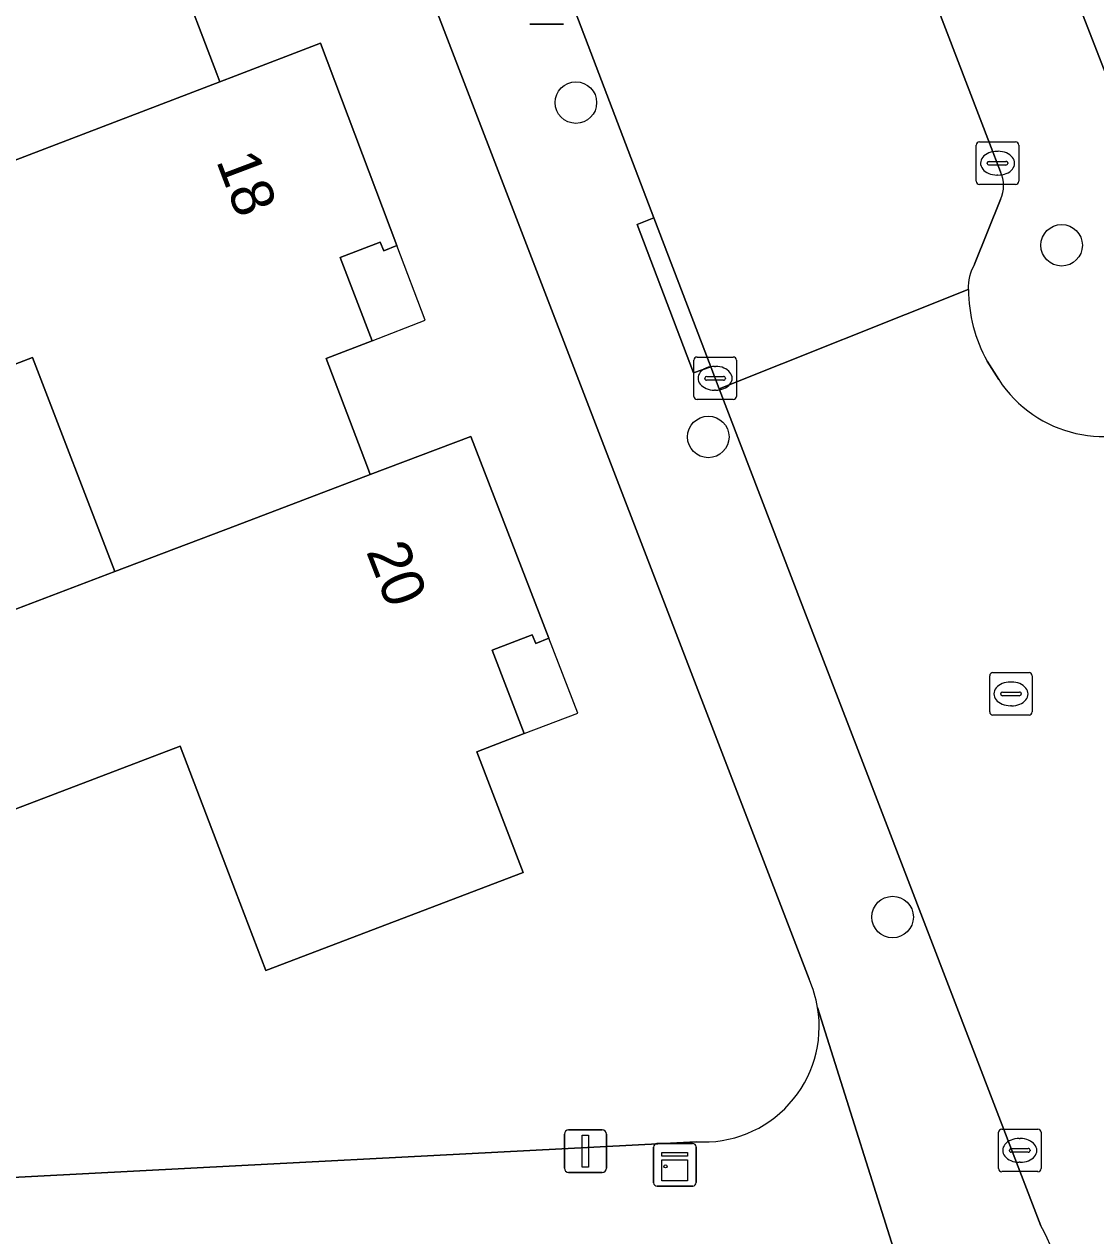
# Model space of a CAD drawing. Extents: x 159262 to 160143, y 383399 to 384319.
# Drawn here: x 159495.03 to 159520.25, y 383645.59 to 383674.12 of the extents above; entities that cross this region are included whole.
import ezdxf

# ---------------------------------------------------------------- set-up
doc = ezdxf.new("R2010")
doc.units = 0
for name, color, linetype in [('IMGEO_Boom', 7, 'Continuous'), ('IMGEO_Erf', 7, 'Continuous'), ('IMGEO_Kast', 7, 'Continuous'), ('IMGEO_Kolk', 7, 'Continuous'), ('IMGEO_Lichtmast', 7, 'Continuous'), ('IMGEO_Pand', 7, 'Continuous'), ('IMGEO_Pand_nummerreeks', 7, 'Continuous'), ('IMGEO_Pand_overbouw', 7, 'Continuous'), ('IMGEO_Rijbaan_lokaal_gesloten', 7, 'Continuous'), ('IMGEO_Rijbaan_lokaal_open', 7, 'Continuous'), ('IMGEO_Rioolput', 7, 'Continuous'), ('IMGEO_Voetpad_open', 7, 'Continuous')]:
    doc.layers.add(name, color=color, linetype=linetype)

msp = doc.modelspace()

# ---------------------------------------------------------------- linework, layer by layer
at = {"layer": 'IMGEO_Boom'}
for centre in [(159508.012, 383672.274), (159519.444, 383668.915), (159511.128, 383664.403), (159515.465, 383653.098)]:
    msp.add_circle(centre, 0.489, dxfattribs=at)
at = {"layer": 'IMGEO_Erf'}
for points in [[(159524.222, 383708.733), (159517.215, 383705.993), (159516.251, 383708.492), (159511.066, 383706.465), (159512.465, 383702.887), (159509.321, 383701.658), (159512.811, 383692.674), (159522.704, 383667.239)], [(159513.499, 383651.634), (159500, 383686.749), (159496.449, 383695.986), (159490.681, 383693.764)], [(159498.598, 383675.488), (159499.565, 383672.949), (159499.634, 383672.767), (159500, 383672.907), (159501.998, 383673.672), (159503.8, 383668.912), (159503.49, 383668.788), (159503.405, 383668.989), (159502.464, 383668.631), (159503.215, 383666.668), (159502.136, 383666.253), (159503.105, 383663.69), (159503.171, 383663.515), (159505.537, 383664.413), (159507.377, 383659.665), (159507.067, 383659.541), (159506.982, 383659.742), (159506.041, 383659.384), (159506.796, 383657.417), (159505.683, 383656.991), (159506.773, 383654.147), (159500.713, 383651.835), (159500, 383653.703), (159498.695, 383657.123), (159492.81, 383654.875)], [(159470.88, 383645.715), (159500, 383647.239), (159510.841, 383647.807)]]:
    msp.add_lwpolyline(points, dxfattribs=at)
msp.add_lwpolyline([(159489.125, 383663.933), (159491.054, 383658.914), (159497.161, 383661.233), (159495.223, 383666.276)], close=True, dxfattribs=at)
for centre, radius, start, end in [((159511.055, 383650.53), 2.682, 9.3498, 24.3004), ((159511.019, 383650.52), 2.719, 266.2475, 9.4403)]:
    msp.add_arc(centre, radius, start, end, dxfattribs=at)
at = {"layer": 'IMGEO_Kast'}
for p, q in [((159509.917, 383647.762), (159510.758, 383647.762)), ((159510.758, 383647.762), (159509.917, 383647.762)), ((159509.842, 383646.837), (159509.842, 383647.678)), ((159509.842, 383647.678), (159509.842, 383646.837)), ((159510.842, 383647.687), (159510.842, 383646.846)), ((159510.842, 383646.846), (159510.842, 383647.687)), ((159510.767, 383646.762), (159509.926, 383646.762)), ((159509.926, 383646.762), (159510.767, 383646.762))]:
    msp.add_line(p, q, dxfattribs=at)
for points in [[(159510.037, 383647.552), (159510.637, 383647.552), (159510.637, 383647.467), (159510.037, 383647.467), (159510.037, 383647.552)], [(159510.037, 383647.377), (159510.637, 383647.377), (159510.637, 383646.888), (159510.037, 383646.888), (159510.037, 383647.377)]]:
    msp.add_lwpolyline(points, dxfattribs=at)
msp.add_circle((159510.121, 383647.226), 0.0377, dxfattribs=at)
for centre, start, end in [((159509.92, 383647.684), 92.4484, 184.2845), ((159509.92, 383647.684), 92.4484, 184.2845), ((159510.764, 383647.684), 2.4484, 94.2845), ((159510.764, 383647.684), 2.4484, 94.2845), ((159509.92, 383646.84), 182.4484, 274.2845), ((159509.92, 383646.84), 182.4484, 274.2845), ((159510.764, 383646.84), 272.4484, 4.2845), ((159510.764, 383646.84), 272.4484, 4.2845)]:
    msp.add_arc(centre, 0.0779, start, end, dxfattribs=at)
at = {"layer": 'IMGEO_Kolk'}
for p, q in [((159517.435, 383670.422), (159517.435, 383671.274)), ((159517.51, 383671.348), (159518.362, 383671.348)), ((159517.923, 383671.128), (159517.948, 383671.128)), ((159518.436, 383671.274), (159518.436, 383670.422)), ((159517.694, 383670.842), (159517.694, 383670.854)), ((159517.737, 383670.891), (159518.135, 383670.891)), ((159518.178, 383670.854), (159518.178, 383670.842)), ((159518.132, 383670.805), (159517.734, 383670.805)), ((159517.946, 383670.568), (159517.921, 383670.568)), ((159518.362, 383670.348), (159517.51, 383670.348)), ((159510.863, 383666.284), (159511.715, 383666.284)), ((159510.788, 383665.358), (159510.788, 383666.21)), ((159511.276, 383666.064), (159511.301, 383666.064)), ((159511.789, 383666.21), (159511.789, 383665.358)), ((159511.047, 383665.778), (159511.047, 383665.79)), ((159511.485, 383665.741), (159511.087, 383665.741)), ((159511.09, 383665.827), (159511.488, 383665.827)), ((159511.531, 383665.79), (159511.531, 383665.778)), ((159511.299, 383665.504), (159511.274, 383665.504)), ((159511.715, 383665.284), (159510.863, 383665.284)), ((159517.958, 383647.176), (159517.958, 383648.028)), ((159518.033, 383648.102), (159518.885, 383648.102)), ((159518.959, 383648.028), (159518.959, 383647.176)), ((159518.446, 383647.882), (159518.471, 383647.882)), ((159518.217, 383647.596), (159518.217, 383647.608)), ((159518.655, 383647.559), (159518.257, 383647.559)), ((159518.26, 383647.645), (159518.658, 383647.645)), ((159518.701, 383647.608), (159518.701, 383647.596)), ((159518.469, 383647.322), (159518.444, 383647.322)), ((159518.885, 383647.102), (159518.033, 383647.102))]:
    msp.add_line(p, q, dxfattribs=at)
for points in [[(159517.435, 383670.422), (159517.435, 383671.274)], [(159517.51, 383671.348), (159518.362, 383671.348)], [(159518.436, 383671.274), (159518.436, 383670.422)], [(159518.362, 383670.348), (159517.51, 383670.348)], [(159510.863, 383666.284), (159511.715, 383666.284)], [(159510.788, 383665.358), (159510.788, 383666.21)], [(159511.789, 383666.21), (159511.789, 383665.358)], [(159511.715, 383665.284), (159510.863, 383665.284)], [(159517.958, 383647.176), (159517.958, 383648.028)], [(159518.033, 383648.102), (159518.885, 383648.102)], [(159518.959, 383648.028), (159518.959, 383647.176)], [(159518.885, 383647.102), (159518.033, 383647.102)]]:
    msp.add_lwpolyline(points, dxfattribs=at)
for centre, radius, start, end in [((159517.512, 383671.272), 0.0765, 91.552, 178.448), ((159517.512, 383671.272), 0.0765, 91.552, 178.448), ((159518.36, 383671.272), 0.0765, 1.552, 88.448), ((159518.36, 383671.272), 0.0765, 1.552, 88.448), ((159517.734, 383670.851), 0.0403, 85.8775, 175.7526), ((159517.731, 383670.841), 0.0366, 178.938, 274.7102), ((159518.135, 383670.848), 0.043, 264.8664, 352.4533), ((159518.139, 383670.853), 0.0386, 1.7309, 96.639), ((159517.512, 383670.424), 0.0765, 181.552, 268.448), ((159517.512, 383670.424), 0.0765, 181.552, 268.448), ((159518.36, 383670.424), 0.0765, 271.552, 358.448), ((159518.36, 383670.424), 0.0765, 271.552, 358.448), ((159510.865, 383666.208), 0.0765, 91.552, 178.448), ((159510.865, 383666.208), 0.0765, 91.552, 178.448), ((159511.713, 383666.208), 0.0765, 1.552, 88.448), ((159511.713, 383666.208), 0.0765, 1.552, 88.448), ((159511.087, 383665.787), 0.0403, 85.8775, 175.7526), ((159511.084, 383665.777), 0.0366, 178.938, 274.7102), ((159511.488, 383665.784), 0.043, 264.8664, 352.4533), ((159511.492, 383665.789), 0.0386, 1.7309, 96.639), ((159510.865, 383665.36), 0.0765, 181.552, 268.448), ((159510.865, 383665.36), 0.0765, 181.552, 268.448), ((159511.713, 383665.36), 0.0765, 271.552, 358.448), ((159511.713, 383665.36), 0.0765, 271.552, 358.448), ((159518.035, 383648.026), 0.0765, 91.552, 178.448), ((159518.035, 383648.026), 0.0765, 91.552, 178.448), ((159518.883, 383648.026), 0.0765, 1.552, 88.448), ((159518.883, 383648.026), 0.0765, 1.552, 88.448), ((159518.257, 383647.605), 0.0403, 85.8775, 175.7526), ((159518.254, 383647.595), 0.0366, 178.938, 274.7102), ((159518.658, 383647.602), 0.043, 264.8664, 352.4533), ((159518.662, 383647.607), 0.0386, 1.7309, 96.639), ((159518.035, 383647.178), 0.0765, 181.552, 268.448), ((159518.035, 383647.178), 0.0765, 181.552, 268.448), ((159518.883, 383647.178), 0.0765, 271.552, 358.448), ((159518.883, 383647.178), 0.0765, 271.552, 358.448)]:
    msp.add_arc(centre, radius, start, end, dxfattribs=at)
for centre, major_axis, ratio, start_param, end_param in [((159517.922, 383670.848), (-0.387, 0.002), 0.722429, 4.712389, 7.853982), ((159517.947, 383670.848), (-0.39, 0.002), 0.717154, 1.570796, 4.712389), ((159511.275, 383665.784), (-0.387, 0.002), 0.722429, 4.712389, 7.853982), ((159511.3, 383665.784), (-0.39, 0.002), 0.717154, 1.570796, 4.712389), ((159518.445, 383647.602), (-0.387, 0.002), 0.722429, 4.712389, 7.853982), ((159518.47, 383647.602), (-0.39, 0.002), 0.717154, 1.570796, 4.712389)]:
    msp.add_ellipse(centre, major_axis=major_axis, ratio=ratio, start_param=start_param, end_param=end_param, dxfattribs=at)
at = {"layer": 'IMGEO_Lichtmast'}
for p, q in [((159507.719, 383674.12), (159506.929, 383674.12)), ((159506.929, 383674.12), (159507.719, 383674.12)), ((159507.842, 383648.084), (159508.632, 383648.084)), ((159508.632, 383648.084), (159507.842, 383648.084)), ((159507.742, 383647.184), (159507.742, 383647.984)), ((159507.742, 383647.984), (159507.742, 383647.184)), ((159508.732, 383647.984), (159508.732, 383647.184)), ((159508.732, 383647.184), (159508.732, 383647.984)), ((159508.632, 383647.084), (159507.842, 383647.084)), ((159507.842, 383647.084), (159508.632, 383647.084))]:
    msp.add_line(p, q, dxfattribs=at)
msp.add_lwpolyline([(159508.162, 383647.959), (159508.312, 383647.959), (159508.312, 383647.209), (159508.162, 383647.209), (159508.162, 383647.959)], dxfattribs=at)
for centre, start, end in [((159507.842, 383647.984), 90, 180), ((159507.842, 383647.984), 90, 180), ((159508.632, 383647.984), 0, 90), ((159508.632, 383647.984), 360, 90), ((159507.842, 383647.184), 180, 270), ((159507.842, 383647.184), 180, 270), ((159508.632, 383647.184), 270, 0), ((159508.632, 383647.184), 270, 0)]:
    msp.add_arc(centre, 0.1, start, end, dxfattribs=at)
at = {"layer": 'IMGEO_Pand'}
for points in [[(159498.598, 383675.488), (159499.696, 383675.913), (159498.941, 383677.872), (159499.882, 383678.23), (159500, 383678.042), (159500.277, 383678.153), (159500, 383678.876), (159498.452, 383682.919), (159496.097, 383682.017), (159490.041, 383679.698), (159483.961, 383677.37), (159485.556, 383673.219), (159491.705, 383675.582), (159493.665, 383670.483), (159499.634, 383672.767), (159499.565, 383672.949)], [(159503.215, 383666.668), (159502.464, 383668.631), (159503.405, 383668.989), (159503.49, 383668.788), (159503.8, 383668.912), (159501.998, 383673.672), (159500, 383672.907), (159499.634, 383672.767), (159493.665, 383670.483), (159487.513, 383668.129), (159489.125, 383663.933), (159495.223, 383666.276), (159497.161, 383661.233), (159500, 383662.311), (159503.171, 383663.515), (159503.105, 383663.69), (159502.136, 383666.253)], [(159505.683, 383656.991), (159506.796, 383657.417), (159506.041, 383659.384), (159506.982, 383659.742), (159507.067, 383659.541), (159507.377, 383659.665), (159505.537, 383664.413), (159503.171, 383663.515), (159500, 383662.311), (159497.161, 383661.233), (159491.054, 383658.914), (159492.632, 383654.807), (159492.81, 383654.875), (159498.695, 383657.123), (159500, 383653.703), (159500.713, 383651.835), (159506.773, 383654.147)]]:
    msp.add_lwpolyline(points, close=True, dxfattribs=at)
at = {"layer": 'IMGEO_Pand_overbouw'}
for points in [[(159503.8, 383668.912), (159503.49, 383668.788), (159503.405, 383668.989), (159502.464, 383668.631), (159503.215, 383666.668), (159504.467, 383667.15)], [(159507.377, 383659.665), (159507.067, 383659.541), (159506.982, 383659.742), (159506.041, 383659.384), (159506.796, 383657.417), (159508.061, 383657.901)]]:
    msp.add_lwpolyline(points, close=True, dxfattribs=at)
at = {"layer": 'IMGEO_Rijbaan_lokaal_gesloten'}
for points in [[(159489.512, 383722.543), (159495.821, 383706.144), (159496.217, 383705.045), (159500, 383695.226), (159500.226, 383694.637), (159502.703, 383688.187), (159504.052, 383684.679), (159504.271, 383684.118), (159506.344, 383678.724), (159507.694, 383675.212), (159509.846, 383669.564), (159511.185, 383666.05), (159511.381, 383665.535), (159517.248, 383667.871)], [(159518.009, 383670.645), (159500.962, 383715.104)], [(159517.397, 383668.469), (159518.008, 383669.995)]]:
    msp.add_lwpolyline(points, dxfattribs=at)
for centre, radius, start, end in [((159517.283, 383670.321), 0.795, 335.7706, 24.0532), ((159518.327, 383667.92), 1.081, 149.4394, 182.5783)]:
    msp.add_arc(centre, radius, start, end, dxfattribs=at)
at = {"layer": 'IMGEO_Rijbaan_lokaal_open'}
for points in [[(159517.248, 383667.871), (159511.381, 383665.535), (159513.341, 383660.438), (159514.686, 383656.939), (159518.958, 383645.83)], [(159517.964, 383665.755), (159517.688, 383666.189)]]:
    msp.add_lwpolyline(points, dxfattribs=at)
for centre, radius, start, end in [((159520.818, 383667.906), 3.57, 180.5674, 208.752), ((159520.44, 383667.363), 2.953, 212.993, 301.1537), ((159514.406, 383643.394), 5.163, 272.5547, 28.154)]:
    msp.add_arc(centre, radius, start, end, dxfattribs=at)
at = {"layer": 'IMGEO_Rioolput'}
for p, q in [((159517.751, 383657.926), (159517.751, 383658.778)), ((159517.826, 383658.852), (159518.678, 383658.852)), ((159518.239, 383658.632), (159518.264, 383658.632)), ((159518.752, 383658.778), (159518.752, 383657.926)), ((159518.01, 383658.346), (159518.01, 383658.358)), ((159518.448, 383658.309), (159518.05, 383658.309)), ((159518.053, 383658.395), (159518.451, 383658.395)), ((159518.494, 383658.358), (159518.494, 383658.346)), ((159518.262, 383658.072), (159518.237, 383658.072)), ((159518.678, 383657.852), (159517.826, 383657.852))]:
    msp.add_line(p, q, dxfattribs=at)
for points in [[(159517.751, 383657.926), (159517.751, 383658.778)], [(159517.826, 383658.852), (159518.678, 383658.852)], [(159518.752, 383658.778), (159518.752, 383657.926)], [(159518.678, 383657.852), (159517.826, 383657.852)]]:
    msp.add_lwpolyline(points, dxfattribs=at)
for centre, radius, start, end in [((159517.828, 383658.776), 0.0765, 91.552, 178.448), ((159517.828, 383658.776), 0.0765, 91.552, 178.448), ((159518.676, 383658.776), 0.0765, 1.552, 88.448), ((159518.676, 383658.776), 0.0765, 1.552, 88.448), ((159518.05, 383658.355), 0.0403, 85.8775, 175.7526), ((159518.047, 383658.345), 0.0366, 178.938, 274.7102), ((159518.451, 383658.352), 0.043, 264.8664, 352.4533), ((159518.455, 383658.357), 0.0386, 1.7309, 96.639), ((159517.828, 383657.928), 0.0765, 181.552, 268.448), ((159517.828, 383657.928), 0.0765, 181.552, 268.448), ((159518.676, 383657.928), 0.0765, 271.552, 358.448), ((159518.676, 383657.928), 0.0765, 271.552, 358.448)]:
    msp.add_arc(centre, radius, start, end, dxfattribs=at)
for centre, major_axis, ratio, start_param, end_param in [((159518.238, 383658.352), (-0.387, 0.002), 0.722429, 4.712389, 7.853982), ((159518.263, 383658.352), (-0.39, 0.002), 0.717154, 1.570796, 4.712389)]:
    msp.add_ellipse(centre, major_axis=major_axis, ratio=ratio, start_param=start_param, end_param=end_param, dxfattribs=at)
at = {"layer": 'IMGEO_Voetpad_open'}
for points in [[(159476.889, 383747.088), (159478.507, 383742.809), (159478.603, 383742.601), (159479.759, 383739.576), (159481.692, 383734.52), (159483.955, 383728.599), (159485.418, 383724.77), (159485.853, 383723.626), (159485.859, 383723.61), (159493.36, 383704.052), (159494.814, 383700.262), (159496.449, 383695.986), (159500, 383686.749), (159513.499, 383651.634)], [(159493.662, 383742.956), (159491.182, 383741.969), (159492.67, 383738.19), (159492.205, 383738.007), (159493.397, 383734.979), (159496.348, 383727.229), (159496.815, 383727.407), (159498.178, 383723.824), (159497.711, 383723.646), (159498.316, 383722.058), (159499.288, 383722.428), (159501.934, 383715.474), (159500.962, 383715.104), (159518.009, 383670.645)], [(159521.968, 383664.836), (159523.427, 383665.372), (159523.264, 383665.799), (159522.704, 383667.239), (159512.811, 383692.674), (159509.321, 383701.658), (159506.408, 383709.106), (159505.749, 383710.795), (159503.698, 383716.375), (159503.16, 383717.83), (159501.344, 383722.528), (159500, 383726.102), (159493.662, 383742.956)], [(159518.958, 383645.83), (159514.686, 383656.939), (159513.341, 383660.438), (159511.381, 383665.535), (159511.185, 383666.05), (159510.783, 383665.91), (159509.452, 383669.407), (159509.846, 383669.564), (159507.694, 383675.212), (159507.28, 383675.042), (159505.918, 383678.564), (159506.344, 383678.724), (159504.271, 383684.118), (159504.052, 383684.679), (159503.644, 383684.513), (159502.299, 383688.013), (159502.703, 383688.187), (159500.226, 383694.637)], [(159518.008, 383669.995), (159517.397, 383668.469)], [(159517.688, 383666.189), (159517.964, 383665.755)], [(159513.701, 383650.966), (159515.76, 383644.423)], [(159515.76, 383644.423), (159513.701, 383650.966)], [(159510.841, 383647.807), (159500, 383647.239), (159470.88, 383645.715), (159461.547, 383642.154), (159459.241, 383641.492), (159454.327, 383641.533), (159452.08, 383641.511), (159438.869, 383641.706)]]:
    msp.add_lwpolyline(points, dxfattribs=at)
msp.add_lwpolyline([(159509.846, 383669.564), (159509.452, 383669.407), (159510.783, 383665.91), (159511.185, 383666.05)], close=True, dxfattribs=at)
for centre, radius, start, end in [((159517.283, 383670.321), 0.795, 335.7706, 24.0532), ((159518.327, 383667.92), 1.081, 149.4394, 182.5783), ((159520.818, 383667.906), 3.57, 180.5674, 208.752), ((159520.44, 383667.363), 2.953, 212.993, 301.1537), ((159511.055, 383650.53), 2.682, 9.3498, 24.3004), ((159511.019, 383650.52), 2.719, 266.2475, 9.4403), ((159514.406, 383643.394), 5.163, 272.5547, 28.154)]:
    msp.add_arc(centre, radius, start, end, dxfattribs=at)

# ---------------------------------------------------------------- texts
at = {"layer": 'IMGEO_Pand_nummerreeks'}
for s, rotation, p in [('18', 290.7294, (159499.539, 383670.905)), ('20', 291.1878, (159503.068, 383661.709))]:
    msp.add_text(s, height=1, rotation=rotation, dxfattribs=at).set_placement(p)

doc.saveas('drawing.dxf')
